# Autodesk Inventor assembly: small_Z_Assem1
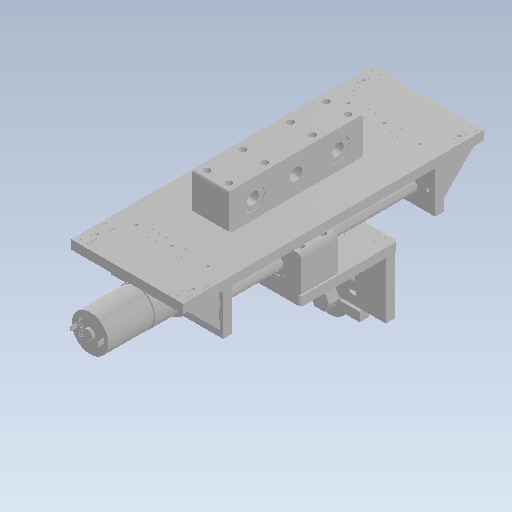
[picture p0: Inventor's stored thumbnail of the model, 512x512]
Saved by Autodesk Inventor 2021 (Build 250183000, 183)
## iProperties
Created: 2026-10
Part Number: small_Z_Assem1
Document SubType Name: Assembly
Designer: hp
Author: hp
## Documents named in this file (19)
- C:\Users\hp\Downloads\small_Z_Assem1.iam
- C:\Users\hp\Downloads\small_Z_Back.ipt
- C:\Users\hp\Downloads\small_Z_Buttom.ipt
- C:\Users\hp\Downloads\small_Z_Top.ipt
- C:\Users\hp\Downloads\rip_1.ipt
- C:\Users\hp\Downloads\rip_2.ipt
- C:\Users\hp\Downloads\rip_3.ipt
- C:\Users\hp\Downloads\rip_4.ipt
- C:\Users\hp\Downloads\z_Bearing_Housing_Assembly.iam
- C:\Users\hp\Downloads\8mm_Bar_150mm.ipt
- C:\Users\hp\Downloads\8mm_Bar_150mm_1.ipt
- C:\Users\hp\Downloads\x_Bearing_Housing.ipt
- C:\Users\hp\Downloads\8mm_Bearing_4.ipt
- C:\Users\hp\Downloads\8mm_Bearing_5.ipt
- C:\Users\hp\Downloads\tool_mout_assembly.iam
- C:\Users\hp\Downloads\688_bearing_1.ipt
- C:\Users\hp\Downloads\Lead Screw T8X8X500_150.ipt
- C:\Users\hp\Downloads\25GA370 red26.ipt
- C:\Users\hp\Downloads\Coupling 4mm x 8mm.ipt
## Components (18 placed, 13 different names)
1. small_Z_Back:1
2. small_Z_Buttom:1
3. small_Z_Top:1
4. rip:3
5. rip:4
6. rip:5
7. rip:6
8. z_Bearing_Housing_Assembly:1 [sub-assembly]
9. 8mm_Bar_150mm:1
10. 8mm_Bar_150mm:2
11. x_Bearing_Housing:1
12. 8mm_Bearing:4
13. 8mm_Bearing:5
14. tool_mout_assembly:1 [sub-assembly]
15. 688_bearing:1
16. Lead Screw T8X8X500_150:1
17. 25GA370 red26:1
18. Coupling 4mm x 8mm:1
